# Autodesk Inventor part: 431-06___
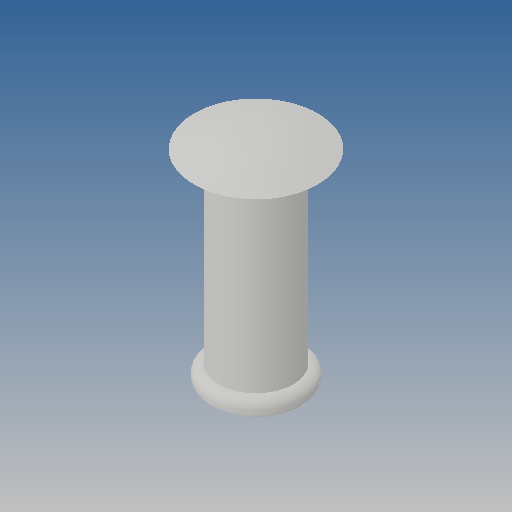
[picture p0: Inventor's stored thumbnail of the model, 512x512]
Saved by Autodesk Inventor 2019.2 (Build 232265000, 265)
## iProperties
Created: 2010-06
Part Number: 431-06___
Material: Ogólny
Document SubType Name: Modeling
Designer: CADENGINEERING4
Density: 1 g/cm^3
Appearance: Domyślna
Author: CADENGINEERING4
Revision Number: ANY
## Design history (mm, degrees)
feature "NONE"
node "Bryła1"
